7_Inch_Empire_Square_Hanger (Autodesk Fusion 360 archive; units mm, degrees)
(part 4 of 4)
sketch "Front_Common_Rafter_Text" plane through (0, 0, 0) normal (0, 1, 0) x axis (1, 0, 0)
  line L1 (177.8, 1.5875) -> (0, 1.5875)
  line L2 (0, 1.5875) -> (0, -176.2125)
  line L3 (0, -176.2125) -> (177.8, 1.5875)
  line L4 (176.2125, 0) -> (0, 0)
  line L5 (131.4823, -11.5032) -> (124.2435, -10.8699)
  line L6 (122.4881, -20.4975) -> (116.3338, -19.4676)
  line L7 (114.45, -28.5356) -> (108.6995, -27.1018)
  line L8 (107.1378, -35.8478) -> (101.7547, -34.0466)
  line L9 (101.1061, -41.8795) -> (96.0261, -39.7753)
  line L10 (95.4139, -47.5716) -> (90.6199, -45.1814)
  line L11 (90.3153, -52.6703) -> (85.2289, -49.704)
  line L12 (85.7136, -57.272) -> (81.407, -54.3944)
  line L13 (81.5404, -61.4451) -> (77.4435, -58.3579)
  line L14 (78.062, -64.9235) -> (74.1399, -61.6615)
  line L15 (74.6142, -68.3713) -> (70.3971, -64.5071)
  line L16 (71.4928, -71.4928) -> (67.4517, -67.4517)
  line L17 (68.6213, -74.3642) -> (65.1735, -70.6278)
  line L18 (65.9917, -76.9938) -> (62.2628, -72.6432)
  line L19 (63.5999, -79.3857) -> (60.4044, -75.397)
  line L20 (61.3178, -81.6677) -> (58.237, -77.5644)
  line L21 (59.1438, -83.8417) -> (56.1722, -79.6292)
  line L22 (57.2071, -85.7784) -> (53.9805, -80.9403)
  line L23 (55.3812, -87.6044) -> (52.5986, -83.2028)
  line L24 (53.6676, -89.3179) -> (50.9711, -84.8302)
  line L25 (51.9346, -91.051) -> (49.3252, -86.4762)
  line L26 (50.4513, -92.5342) -> (47.9164, -87.8849)
  line L27 (49.0883, -93.8973) -> (46.3277, -88.6167)
  line L28 (47.7103, -95.2753) -> (45.3132, -90.4883)
  line L29 (134.6309, -8.3546) -> (41.6921, -101.2934)
  line L30 (131.0388, -4.7625) -> (38.1, -97.7013)
  line L31 (133.7069, -12.8708) -> (135.864, -10.7136)
  line L32 (134.7855, -11.7922) -> (131.4823, -11.5032)
  line L33 (131.4823, -11.5032) -> (124.8761, -10.9252)
  line L34 (125.5652, -21.0124) -> (122.4881, -20.4975)
  line L35 (124.4929, -22.0847) -> (126.6376, -19.9401)
  line L36 (117.3252, -29.2525) -> (114.45, -28.5356)
  line L37 (119.0808, -27.4969) -> (115.5696, -31.0081)
  line L38 (109.8293, -36.7484) -> (107.1378, -35.8478)
  line L39 (103.6461, -42.9316) -> (101.1061, -41.8795)
  line L40 (97.8109, -48.7667) -> (95.4139, -47.5716)
  line L41 (92.5842, -53.9935) -> (90.3153, -52.6703)
  line L42 (87.8669, -58.7108) -> (85.7136, -57.272)
  line L43 (104.7965, -41.7812) -> (102.4956, -44.0821)
  line L44 (98.9884, -47.5892) -> (96.6334, -49.9442)
  line L45 (93.6043, -52.9734) -> (91.5641, -55.0136)
  line L46 (89.01, -57.5676) -> (86.7237, -59.8539)
  line L47 (83.5889, -62.9888) -> (81.5404, -61.4451)
  line L48 (48.9089, -97.6688) -> (47.7103, -95.2753)
  line L49 (50.3215, -96.2562) -> (49.0883, -93.8973)
  line L50 (51.7188, -94.8589) -> (50.4513, -92.5342)
  line L51 (53.2393, -93.3384) -> (51.9346, -91.051)
  line L52 (55.0159, -91.5618) -> (53.6676, -89.3179)
  line L53 (56.7725, -89.8052) -> (55.3812, -87.6044)
  line L54 (58.6443, -87.9334) -> (57.2071, -85.7784)
  line L55 (60.6296, -85.948) -> (59.1438, -83.8417)
  line L56 (62.8583, -83.7194) -> (61.3178, -81.6677)
  line L57 (65.1977, -81.38) -> (63.5999, -79.3857)
  line L58 (67.6496, -78.9281) -> (65.9917, -76.9938)
  line L59 (70.3452, -76.2324) -> (68.6213, -74.3642)
  line L60 (73.2888, -73.2888) -> (71.4928, -71.4928)
  line L61 (76.4887, -70.089) -> (74.6142, -68.3713)
  line L62 (80.0231, -66.5545) -> (78.062, -64.9235)
  line L63 (84.8131, -61.7645) -> (82.3647, -64.213)
  line L64 (81.1425, -65.4352) -> (78.9038, -67.6739)
  line L65 (77.5939, -68.9838) -> (75.3835, -71.1941)
  line L66 (74.3554, -72.2223) -> (72.2223, -74.3554)
  line L67 (71.4477, -75.13) -> (69.2428, -77.3349)
  line L68 (68.6194, -77.9583) -> (66.6798, -79.8979)
  line L69 (65.9607, -80.6169) -> (64.4346, -82.143)
  line L70 (63.6278, -82.9499) -> (62.0888, -84.4888)
  line L71 (61.3516, -85.2261) -> (59.9077, -86.67)
  line L72 (59.0519, -87.5258) -> (58.2367, -88.341)
  line L73 (57.1706, -89.407) -> (56.3743, -90.2033)
  line L74 (55.3816, -91.1961) -> (54.6502, -91.9275)
  line L75 (53.6549, -92.9227) -> (52.8236, -93.754)
  line L76 (52.0292, -94.5485) -> (51.4083, -95.1693)
  line L77 (50.7174, -95.8602) -> (49.9256, -96.6521)
  line L78 (49.3359, -97.2417) -> (48.4818, -98.0958)
  line L79 (110.6422, -35.9355) -> (109.0164, -37.5613)
  line L80 (30.6283, -115.9494) -> (40.2487, -106.329)
  point P11 (131.4823, -11.5032)
  point P64 (131.4823, -11.5032)
  point P65 (134.7855, -11.7922)
  point P68 (125.5652, -21.0124)
  point P13 (122.4881, -20.4975)
  point P71 (122.4881, -20.4975)
  point P15 (114.45, -28.5356)
  point P72 (114.45, -28.5356)
  point P73 (117.3252, -29.2525)
  point P17 (107.1378, -35.8478)
  point P76 (107.1378, -35.8478)
  point P19 (101.1061, -41.8795)
  point P78 (101.1061, -41.8795)
  point P21 (95.4139, -47.5716)
  point P80 (95.4139, -47.5716)
  point P23 (90.3153, -52.6703)
  point P82 (90.3153, -52.6703)
  point P25 (85.7136, -57.272)
  point P84 (85.7136, -57.272)
  point P27 (81.5404, -61.4451)
  point P94 (81.5404, -61.4451)
  point P57 (47.7103, -95.2753)
  point P96 (47.7103, -95.2753)
  point P55 (49.0883, -93.8973)
  point P98 (49.0883, -93.8973)
  point P53 (50.4513, -92.5342)
  point P100 (50.4513, -92.5342)
  point P51 (51.9346, -91.051)
  point P102 (51.9346, -91.051)
  point P49 (53.6676, -89.3179)
  point P104 (53.6676, -89.3179)
  point P47 (55.3812, -87.6044)
  point P106 (55.3812, -87.6044)
  point P45 (57.2071, -85.7784)
  point P108 (57.2071, -85.7784)
  point P43 (59.1438, -83.8417)
  point P110 (59.1438, -83.8417)
  point P41 (61.3178, -81.6677)
  point P112 (61.3178, -81.6677)
  point P39 (63.5999, -79.3857)
  point P114 (63.5999, -79.3857)
  point P37 (65.9917, -76.9938)
  point P116 (65.9917, -76.9938)
  point P35 (68.6213, -74.3642)
  point P118 (68.6213, -74.3642)
  point P33 (71.4928, -71.4928)
  point P120 (71.4928, -71.4928)
  point P31 (74.6142, -68.3713)
  point P122 (74.6142, -68.3713)
  point P29 (78.062, -64.9235)
  point P124 (78.062, -64.9235)
  point P97 (48.9089, -97.6688)
  point P99 (50.3215, -96.2562)
  point P101 (51.7188, -94.8589)
  point P103 (53.2393, -93.3384)
  point P105 (55.0159, -91.5618)
  point P107 (56.7725, -89.8052)
  point P109 (58.6443, -87.9334)
  point P111 (60.6296, -85.948)
  point P113 (62.8583, -83.7194)
  point P115 (65.1977, -81.38)
  point P117 (67.6496, -78.9281)
  point P119 (70.3452, -76.2324)
  point P121 (73.2888, -73.2888)
  point P123 (76.4887, -70.089)
  point P125 (80.0231, -66.5545)
  point P95 (83.5889, -62.9888)
  point P85 (87.8669, -58.7108)
  point P83 (92.5842, -53.9935)
  point P81 (97.8109, -48.7667)
  point P79 (103.6461, -42.9316)
  point P77 (109.8293, -36.7484)
  point P162 (35.4385, -111.1392)
  point P62 (135.864, -10.7136)
  coincident P11 P64
  midpoint L31 P65
  parallel L32 L33
  parallel L29 L31
  midpoint P68 L35
  coincident P13 P71
  parallel L6 L34
  collinear L31 L35
  coincident P15 P72
  parallel L7 L36
  midpoint P73 L37
  collinear L35 L37
  coincident P17 P76
  parallel L8 L38
  coincident P19 P78
  parallel L9 L39
  coincident P21 P80
  parallel L10 L40
  coincident P23 P82
  parallel L11 L41
  coincident P25 P84
  parallel L12 L42
  coincident P27 P94
  parallel L13 L47
  coincident P57 P96
  parallel L28 L48
  coincident P55 P98
  parallel L27 L49
  coincident P53 P100
  parallel L26 L50
  coincident P51 P102
  parallel L25 L51
  coincident P49 P104
  parallel L24 L52
  coincident P47 P106
  parallel L23 L53
  coincident P45 P108
  parallel L22 L54
  coincident P43 P110
  parallel L21 L55
  coincident P41 P112
  parallel L20 L56
  coincident P39 P114
  parallel L19 L57
  coincident P37 P116
  parallel L18 L58
  coincident P35 P118
  coincident P33 P120
  parallel L17 L59
  parallel L16 L60
  coincident P31 P122
  parallel L15 L61
  coincident P29 P124
  parallel L14 L62
  midpoint P97 L78
  midpoint P99 L77
  midpoint P101 L76
  midpoint P103 L75
  midpoint P105 L74
  midpoint P107 L73
  midpoint P109 L72
  midpoint P111 L71
  midpoint P113 L70
  midpoint P115 L69
  midpoint P117 L68
  midpoint P119 L67
  midpoint P121 L66
  midpoint P123 L65
  midpoint P125 L64
  midpoint P95 L63
  midpoint P85 L46
  midpoint P83 L45
  midpoint P81 L44
  midpoint P79 L43
  midpoint P77 L79
  collinear L37 L79
  collinear L43 L79
  collinear L43 L44
  collinear L44 L45
  collinear L45 L46
  collinear L46 L63
  collinear L63 L64
  collinear L64 L65
  collinear L65 L66
  collinear L66 L67
  collinear L67 L68
  collinear L68 L69
  collinear L69 L70
  collinear L70 L71
  collinear L71 L72
  collinear L72 L73
  collinear L73 L74
  collinear L74 L75
  collinear L75 L76
  collinear L76 L77
  collinear L77 L78
  collinear L78 L80
  midpoint L80 P162
  dimension "d956" distance L29 P62 = 2.54
  dimension "d1030" distance P97 P162 = 19.05
  dimension "d957" Text1-Height = 3.175
  dimension "d958" Text2-Height = 3.175
  dimension "d959" Text3-Height = 3.175
  dimension "d960" Text4-Height = 3.175
  dimension "d961" Text5-Height = 3.175
  dimension "d962" Text6-Height = 3.175
  dimension "d963" Text7-Height = 3.175
  dimension "d964" Text8-Height = 3.175
  dimension "d965" Text9-Height = 3.175
  dimension "d966" Text10-Height = 3.175
  dimension "d968" Text11-Height = 3.175
  dimension "d969" Text12-Height = 3.175
  dimension "d970" Text13-Height = 3.175
  dimension "d971" Text14-Height = 3.175
  dimension "d1029" Text15-Height = 3.175
sketch "Back_Common_Rafter_Text" plane through (0, 0, 0) normal (0, 1, 0) x axis (1, 0, 0)
  line L1 (71.4477, -75.13) -> (69.2428, -77.3349)
  line L2 (70.3452, -76.2324) -> (68.6212, -74.3641)
  line L3 (63.6278, -82.9499) -> (62.0888, -84.4888)
  line L4 (65.1977, -81.38) -> (63.5997, -79.3854)
  line L5 (89.01, -57.5676) -> (86.7237, -59.8539)
  line L6 (73.2888, -73.2888) -> (71.4922, -71.4922)
  line L7 (65.9915, -76.9936) -> (62.2628, -72.6432)
  line L8 (68.6194, -77.9583) -> (66.6798, -79.8979)
  line L9 (67.6496, -78.9281) -> (65.9915, -76.9936)
  line L10 (76.4887, -70.089) -> (74.6141, -68.3712)
  line L11 (62.8583, -83.7194) -> (61.3178, -81.6677)
  line L12 (77.5939, -68.9838) -> (75.3835, -71.1941)
  line L13 (110.6422, -35.9355) -> (109.0164, -37.5612)
  line L14 (68.6212, -74.3641) -> (65.1735, -70.6278)
  line L15 (84.8131, -61.7645) -> (82.3647, -64.213)
  line L16 (98.9884, -47.5892) -> (96.6334, -49.9442)
  line L17 (124.4929, -22.0847) -> (126.6376, -19.9401)
  line L18 (104.7965, -41.7811) -> (102.4956, -44.0821)
  line L19 (65.9607, -80.6169) -> (64.4346, -82.143)
  line L20 (59.0519, -87.5258) -> (58.2367, -88.341)
  line L21 (133.7069, -12.8708) -> (135.864, -10.7136)
  line L22 (119.0811, -27.4965) -> (115.5693, -31.0084)
  line L23 (74.3554, -72.2223) -> (72.2223, -74.3554)
  line L24 (81.1425, -65.4352) -> (78.9038, -67.6739)
  line L25 (93.6053, -52.9723) -> (91.5651, -55.0125)
  line L26 (49.3359, -97.2418) -> (48.4819, -98.0958)
  line L27 (53.6549, -92.9227) -> (52.8236, -93.7541)
  line L28 (61.3516, -85.2261) -> (59.9077, -86.67)
  line L29 (48.9089, -97.6688) -> (47.7103, -95.2753)
  line L30 (61.3178, -81.6677) -> (58.237, -77.5644)
  line L31 (63.5997, -79.3854) -> (60.4044, -75.397)
  line L32 (71.4922, -71.4922) -> (67.4517, -67.4517)
  line L33 (74.6141, -68.3712) -> (70.3971, -64.5071)
  line L34 (90.3157, -52.6694) -> (85.2289, -49.704)
  line L35 (134.7855, -11.7922) -> (131.4328, -11.4989)
  line L36 (103.6461, -42.9316) -> (101.1059, -41.8794)
  line L37 (114.45, -28.5356) -> (108.6995, -27.1018)
  line L38 (87.8669, -58.7108) -> (85.7135, -57.2719)
  line L39 (107.1376, -35.8477) -> (101.7547, -34.0466)
  line L40 (125.5652, -21.0124) -> (122.4881, -20.4975)
  line L41 (55.3808, -87.6038) -> (52.5986, -83.2028)
  line L42 (57.1706, -89.407) -> (56.3743, -90.2033)
  line L43 (101.1059, -41.8794) -> (96.0261, -39.7753)
  line L44 (97.8109, -48.7667) -> (95.4136, -47.5715)
  line L45 (122.4881, -20.4975) -> (116.3338, -19.4676)
  line L46 (53.2393, -93.3384) -> (51.9336, -91.0493)
  line L47 (55.0159, -91.5618) -> (53.6671, -89.317)
  line L48 (81.5404, -61.4451) -> (77.4435, -58.3579)
  line L49 (83.5889, -62.9888) -> (81.5404, -61.4451)
  line L50 (78.0619, -64.9234) -> (74.1399, -61.6615)
  line L51 (117.3252, -29.2525) -> (114.45, -28.5356)
  line L52 (57.2071, -85.7784) -> (53.9805, -80.9403)
  line L53 (80.0231, -66.5545) -> (78.0619, -64.9234)
  line L54 (47.7103, -95.2753) -> (45.3132, -90.4883)
  line L55 (85.7135, -57.2719) -> (81.407, -54.3944)
  line L56 (92.5852, -53.9924) -> (90.3157, -52.6694)
  line L57 (51.9336, -91.0493) -> (49.3252, -86.4762)
  line L58 (51.7188, -94.8589) -> (50.4504, -92.5326)
  line L59 (50.7174, -95.8602) -> (49.9256, -96.6521)
  line L60 (131.4328, -11.4989) -> (124.2435, -10.8699)
  line L61 (109.8293, -36.7484) -> (107.1376, -35.8477)
  line L62 (50.3215, -96.2562) -> (49.0879, -93.8964)
  line L63 (56.7725, -89.8052) -> (55.3808, -87.6038)
  line L64 (52.0292, -94.5485) -> (51.4083, -95.1693)
  line L65 (59.1427, -83.8401) -> (56.1722, -79.6292)
  line L66 (131.4823, -11.5032) -> (124.8761, -10.9252)
  line L67 (58.6443, -87.9334) -> (57.2071, -85.7784)
  line L68 (50.4504, -92.5326) -> (47.9164, -87.8849)
  line L69 (53.6671, -89.317) -> (50.9711, -84.8302)
  line L70 (60.6296, -85.948) -> (59.1427, -83.8401)
  line L71 (95.4136, -47.5715) -> (90.6199, -45.1814)
  line L72 (49.0879, -93.8964) -> (46.3277, -88.6167)
  line L73 (55.3816, -91.1961) -> (54.6502, -91.9275)
  line L74 (176.2125, 0) -> (0, 0)
  line L75 (177.8, 1.5875) -> (0, 1.5875)
  line L76 (0, 1.5875) -> (0, -176.2125)
  line L77 (0, -176.2125) -> (177.8, 1.5875)
  line L78 (49.0883, -93.8973) -> (46.3277, -88.6167)
  line L79 (50.4513, -92.5342) -> (47.9164, -87.8849)
  line L80 (51.9346, -91.051) -> (49.3252, -86.4762)
  line L81 (53.6676, -89.3179) -> (50.9711, -84.8302)
  line L82 (48.9089, -97.6688) -> (47.7103, -95.2753)
  line L83 (55.3812, -87.6044) -> (52.5986, -83.2028)
  line L84 (59.1438, -83.8417) -> (56.1722, -79.6292)
  line L85 (63.5999, -79.3857) -> (60.4044, -75.397)
  line L86 (65.9917, -76.9938) -> (62.2628, -72.6432)
  line L87 (68.6213, -74.3642) -> (65.1735, -70.6278)
  line L88 (71.4928, -71.4928) -> (67.4517, -67.4517)
  line L89 (74.6142, -68.3713) -> (70.3971, -64.5071)
  line L90 (78.062, -64.9235) -> (74.1399, -61.6615)
  line L91 (81.5404, -61.4451) -> (77.4435, -58.3579)
  line L92 (85.7136, -57.272) -> (81.407, -54.3944)
  line L93 (95.4139, -47.5716) -> (90.6199, -45.1814)
  line L94 (101.1061, -41.8795) -> (96.0261, -39.7753)
  line L95 (107.1378, -35.8478) -> (101.7547, -34.0466)
  line L96 (114.45, -28.5356) -> (108.6995, -27.1018)
  line L97 (131.4823, -11.5032) -> (124.8761, -10.9252)
  line L98 (131.4823, -11.5032) -> (124.2435, -10.8699)
  line L99 (131.0388, -4.7625) -> (38.1, -97.7013)
  line L100 (134.6309, -8.3546) -> (41.6921, -101.2934)
  line L101 (125.5652, -21.0124) -> (122.4881, -20.4975)
  line L102 (62.8583, -83.7194) -> (61.3178, -81.6677)
  line L103 (30.6283, -115.9494) -> (40.2487, -106.329)
  point P16 (131.4328, -11.4989)
  point P79 (131.4328, -11.4989)
  point P82 (134.7855, -11.7922)
  point P8 (125.5652, -21.0124)
  point P11 (122.4881, -20.4975)
  point P23 (122.4881, -20.4975)
  point P4 (114.45, -28.5356)
  point P26 (114.45, -28.5356)
  point P5 (117.3252, -29.2525)
  point P24 (107.1376, -35.8477)
  point P51 (107.1376, -35.8477)
  point P27 (101.1059, -41.8794)
  point P52 (101.1059, -41.8794)
  point P18 (95.4136, -47.5715)
  point P116 (95.4136, -47.5715)
  point P31 (90.3157, -52.6694)
  point P67 (90.3157, -52.6694)
  point P35 (85.7135, -57.2719)
  point P114 (85.7135, -57.2719)
  point P68 (81.5404, -61.4451)
  point P130 (81.5404, -61.4451)
  point P85 (47.7103, -95.2753)
  point P136 (47.7103, -95.2753)
  point P69 (49.0879, -93.8964)
  point P88 (49.0879, -93.8964)
  point P89 (50.4504, -92.5326)
  point P138 (50.4504, -92.5326)
  point P38 (51.9336, -91.0493)
  point P84 (51.9336, -91.0493)
  point P58 (53.6671, -89.317)
  point P77 (53.6671, -89.317)
  point P76 (55.3808, -87.6038)
  point P128 (55.3808, -87.6038)
  point P34 (59.1427, -83.8401)
  point P107 (59.1427, -83.8401)
  point P105 (61.3178, -81.6677)
  point P142 (61.3178, -81.6677)
  point P103 (63.5997, -79.3854)
  point P110 (63.5997, -79.3854)
  point P101 (65.9915, -76.9936)
  point P115 (65.9915, -76.9936)
  point P50 (68.6212, -74.3641)
  point P60 (68.6212, -74.3641)
  point P2 (71.4922, -71.4922)
  point P48 (71.4922, -71.4922)
  point P29 (74.6141, -68.3712)
  point P65 (74.6141, -68.3712)
  point P113 (78.0619, -64.9234)
  point P123 (78.0619, -64.9234)
  point P137 (48.9089, -97.6688)
  point P70 (50.3215, -96.2562)
  point P140 (51.7188, -94.8589)
  point P44 (53.2393, -93.3384)
  point P54 (55.0159, -91.5618)
  point P124 (56.7725, -89.8052)
  point P41 (58.6443, -87.9334)
  point P108 (60.6296, -85.948)
  point P133 (62.8583, -83.7194)
  point P147 (65.1977, -81.38)
  point P62 (67.6496, -78.9281)
  point P64 (70.3452, -76.2324)
  point P3 (73.2888, -73.2888)
  point P63 (76.4887, -70.089)
  point P126 (80.0231, -66.5545)
  point P139 (83.5889, -62.9888)
  point P33 (87.8669, -58.7108)
  point P32 (92.5852, -53.9924)
  point P117 (97.8109, -48.7667)
  point P118 (103.6461, -42.9316)
  point P53 (109.8293, -36.7484)
  point P90 (45.3132, -90.4883)
  point P156 (45.3132, -90.4883)
  point P86 (46.3277, -88.6167)
  point P157 (46.3277, -88.6167)
  point P80 (47.9164, -87.8849)
  point P160 (47.9164, -87.8849)
  point P78 (49.3252, -86.4762)
  point P163 (49.3252, -86.4762)
  point P75 (50.9711, -84.8302)
  point P166 (50.9711, -84.8302)
  point P169 (47.7103, -95.2753)
  point P74 (52.5986, -83.2028)
  point P172 (52.5986, -83.2028)
  point P73 (53.9805, -80.9403)
  point P175 (53.9805, -80.9403)
  point P30 (56.1722, -79.6292)
  point P176 (56.1722, -79.6292)
  point P104 (58.237, -77.5644)
  point P179 (58.237, -77.5644)
  point P102 (60.4044, -75.397)
  point P180 (60.4044, -75.397)
  point P49 (62.2628, -72.6432)
  point P183 (62.2628, -72.6432)
  point P47 (65.1735, -70.6278)
  point P186 (65.1735, -70.6278)
  point P46 (67.4517, -67.4517)
  point P189 (67.4517, -67.4517)
  point P28 (70.3971, -64.5071)
  point P192 (70.3971, -64.5071)
  point P111 (74.1399, -61.6615)
  point P195 (74.1399, -61.6615)
  point P20 (77.4435, -58.3579)
  point P198 (77.4435, -58.3579)
  point P112 (81.407, -54.3944)
  point P201 (81.407, -54.3944)
  point P17 (85.2289, -49.704)
  point P204 (85.2289, -49.704)
  point P15 (90.6199, -45.1814)
  point P205 (90.6199, -45.1814)
  point P21 (96.0261, -39.7753)
  point P208 (96.0261, -39.7753)
  point P25 (101.7547, -34.0466)
  point P211 (101.7547, -34.0466)
  point P14 (108.6995, -27.1018)
  point P214 (108.6995, -27.1018)
  point P22 (116.3338, -19.4676)
  point P217 (116.3338, -19.4676)
  point P81 (124.8761, -10.9252)
  point P218 (124.8761, -10.9252)
  point P19 (124.2435, -10.8699)
  point P221 (124.2435, -10.8699)
  point P228 (122.4881, -20.4975)
  point P231 (61.3178, -81.6677)
  point P43 (57.2071, -85.7784)
  point P234 (57.2071, -85.7784)
  coincident P16 P79
  midpoint P82 L21
  parallel L35 L66
  midpoint P8 L17
  coincident P11 P23
  parallel L40 L45
  collinear L17 L21
  coincident P4 P26
  parallel L37 L51
  midpoint P5 L22
  collinear L17 L22
  coincident P24 P51
  parallel L39 L61
  coincident P27 P52
  parallel L36 L43
  coincident P18 P116
  parallel L44 L71
  coincident P31 P67
  parallel L34 L56
  coincident P35 P114
  parallel L38 L55
  coincident P68 P130
  parallel L48 L49
  coincident P85 P136
  parallel L29 L54
  coincident P69 P88
  parallel L62 L72
  coincident P89 P138
  parallel L58 L68
  coincident P38 P84
  parallel L46 L57
  coincident P58 P77
  parallel L47 L69
  coincident P76 P128
  parallel L41 L63
  parallel L52 L67
  coincident P34 P107
  parallel L65 L70
  coincident P105 P142
  parallel L11 L30
  coincident P103 P110
  parallel L4 L31
  coincident P101 P115
  parallel L7 L9
  coincident P50 P60
  coincident P2 P48
  parallel L2 L14
  parallel L6 L32
  coincident P29 P65
  parallel L10 L33
  coincident P113 P123
  parallel L50 L53
  midpoint P137 L26
  midpoint P70 L59
  midpoint P140 L64
  midpoint P44 L27
  midpoint P54 L73
  midpoint P124 L42
  midpoint P41 L20
  midpoint P108 L28
  midpoint P133 L3
  midpoint P147 L19
  midpoint P62 L8
  midpoint P64 L1
  midpoint P3 L23
  midpoint P63 L12
  midpoint P126 L24
  midpoint P139 L15
  midpoint P33 L5
  midpoint P32 L25
  midpoint P117 L16
  midpoint P118 L18
  midpoint P53 L13
  collinear L13 L22
  collinear L13 L18
  collinear L16 L18
  collinear L16 L25
  collinear L5 L25
  collinear L5 L15
  collinear L15 L24
  collinear L12 L24
  collinear L12 L23
  collinear L1 L23
  collinear L1 L8
  collinear L8 L19
  collinear L3 L19
  collinear L3 L28
  collinear L20 L28
  collinear L20 L42
  collinear L42 L73
  collinear L27 L73
  collinear L27 L64
  collinear L59 L64
  collinear L26 L59
  coincident P90 P156
  coincident P86 P157
  parallel L72 L78
  coincident P80 P160
  parallel L68 L79
  coincident P78 P163
  parallel L57 L80
  coincident P75 P166
  parallel L69 L81
  coincident P136 P169
  coincident P74 P172
  parallel L41 L83
  coincident P73 P175
  coincident P30 P176
  parallel L65 L84
  coincident P104 P179
  coincident P102 P180
  parallel L31 L85
  coincident P49 P183
  parallel L7 L86
  coincident P47 P186
  parallel L14 L87
  coincident P46 P189
  parallel L32 L88
  coincident P28 P192
  parallel L33 L89
  coincident P111 P195
  parallel L50 L90
  coincident P20 P198
  parallel L48 L91
  coincident P112 P201
  parallel L55 L92
  coincident P17 P204
  coincident P15 P205
  parallel L71 L93
  coincident P21 P208
  parallel L43 L94
  coincident P25 P211
  parallel L39 L95
  coincident P14 P214
  parallel L37 L96
  coincident P22 P217
  coincident P81 P218
  parallel L66 L97
  coincident P19 P221
  parallel L60 L98
  coincident P11 P228
  parallel L21 L100
  coincident P142 L100
  coincident P142 P231
  coincident P43 P234
  dimension "d988" distance L21 L100 = 2.54
  dimension "d972" Text1-Height = 3.175
  dimension "d973" Text2-Height = 3.175
  dimension "d974" Text3-Height = 3.175
  dimension "d975" Text4-Height = 3.175
  dimension "d976" Text5-Height = 3.175
  dimension "d977" Text6-Height = 3.175
  dimension "d978" Text7-Height = 3.175
  dimension "d979" Text8-Height = 3.175
  dimension "d980" Text9-Height = 3.175
  dimension "d981" Text10-Height = 3.175
  dimension "d982" Text11-Height = 3.175
  dimension "d983" Text12-Height = 3.175
  dimension "d984" Text13-Height = 3.175
  dimension "d985" Text14-Height = 3.175
  dimension "d1031" Text15-Height = 3.175
sketch "Front_Hip-Valley_Text" plane through (0, 0, 0) normal (0, 1, 0) x axis (1, 0, 0)
  line L1 (0, 1.5875) -> (0, -176.2125)
  line L2 (177.8, 1.5875) -> (0, 1.5875)
  line L3 (0, -176.2125) -> (177.8, 1.5875)
  line L4 (34.5079, -85.129) -> (118.4665, -1.1704)
  line L5 (38.1, -88.7211) -> (122.0586, -4.7625)
  line L6 (52.8926, -74.8136) -> (49.5505, -70.0864)
  line L7 (54.2202, -73.4888) -> (50.7931, -68.8438)
  line L8 (55.6191, -72.0926) -> (52.1025, -67.5344)
  line L9 (57.0778, -70.6363) -> (53.4679, -66.169)
  line L10 (58.6192, -69.0969) -> (54.911, -64.7259)
  line L11 (60.255, -67.4627) -> (56.4427, -63.1942)
  line L12 (61.9752, -65.7435) -> (58.0535, -61.5834)
  line L13 (63.8038, -63.9153) -> (59.7662, -59.8706)
  line L14 (65.7435, -61.9752) -> (61.5834, -58.0535)
  line L15 (67.798, -59.9194) -> (63.5085, -56.1284)
  line L16 (69.9838, -57.7312) -> (65.5572, -54.0797)
  line L17 (72.3191, -55.3922) -> (67.7468, -51.8901)
  line L18 (74.8021, -52.9041) -> (70.0756, -49.5613)
  line L19 (77.4796, -50.2198) -> (72.5878, -47.0491)
  line L20 (80.3449, -47.3457) -> (75.2774, -44.3595)
  line L21 (83.4307, -44.2489) -> (78.1753, -41.4616)
  line L22 (86.7641, -40.9021) -> (81.3072, -38.3296)
  line L23 (90.3668, -37.2834) -> (84.694, -34.9429)
  line L24 (94.2953, -33.3362) -> (88.3888, -31.2481)
  line L25 (98.5635, -29.0462) -> (92.4054, -27.2315)
  line L26 (103.2529, -24.3319) -> (96.8208, -22.8161)
  line L27 (108.3869, -19.1701) -> (101.6571, -17.9798)
  line L28 (114.0839, -13.4422) -> (107.0263, -12.6106)
  line L29 (117.1566, -10.3529) -> (109.9232, -9.7137)
  line L30 (106.6227, -9.422) -> (109.9232, -9.7137)
  line L31 (103.8128, -12.2319) -> (107.0263, -12.6106)
  line L32 (98.6048, -17.4399) -> (101.6571, -17.9798)
  line L33 (93.9137, -22.131) -> (96.8208, -22.8161)
  line L34 (89.631, -26.4138) -> (92.4054, -27.2315)
  line L35 (85.735, -30.3098) -> (88.3888, -31.2481)
  line L36 (82.151, -33.8938) -> (84.694, -34.9429)
  line L37 (78.866, -37.1788) -> (81.3072, -38.3296)
  line L38 (75.8281, -40.2167) -> (78.1753, -41.4616)
  line L39 (73.0172, -43.0276) -> (75.2774, -44.3595)
  line L40 (70.4084, -45.6364) -> (72.5878, -47.0491)
  line L41 (67.9716, -48.0732) -> (70.0756, -49.5613)
  line L42 (65.7127, -50.3321) -> (67.7468, -51.8901)
  line L43 (63.5889, -52.4559) -> (65.5572, -54.0797)
  line L44 (61.6017, -54.4431) -> (63.5085, -56.1284)
  line L45 (59.7343, -56.3105) -> (61.5834, -58.0535)
  line L46 (57.9718, -58.073) -> (59.7662, -59.8706)
  line L47 (56.3105, -59.7343) -> (58.0535, -61.5834)
  line L48 (54.748, -61.2968) -> (56.4427, -63.1942)
  line L49 (53.2623, -62.7825) -> (54.911, -64.7259)
  line L50 (51.8626, -64.1822) -> (53.4679, -66.169)
  line L51 (50.5381, -65.5067) -> (52.1025, -67.5344)
  line L52 (49.268, -66.7767) -> (50.7931, -68.8438)
  line L53 (48.0627, -67.982) -> (49.5505, -70.0864)
  line L54 (103.1183, -12.9265) -> (104.5074, -11.5374)
  line L55 (97.292, -18.7528) -> (99.9177, -16.1271)
  line L56 (92.1996, -23.8452) -> (95.6279, -20.4169)
  line L57 (88.2354, -27.8094) -> (91.0265, -25.0183)
  line L58 (84.4206, -31.6242) -> (87.0493, -28.9955)
  line L59 (80.7488, -35.2959) -> (83.5532, -32.4916)
  line L60 (77.7876, -38.2571) -> (79.9443, -36.1004)
  line L61 (74.8024, -41.2424) -> (76.8537, -39.191)
  line L62 (72.0594, -43.9854) -> (73.975, -42.0698)
  line L63 (69.9763, -46.0685) -> (70.8404, -45.2044)
  line L64 (67.268, -48.7767) -> (68.6752, -47.3696)
  line L65 (65.1884, -50.8563) -> (66.237, -49.8078)
  line L66 (63.0246, -53.0202) -> (64.1532, -51.8916)
  line L67 (60.777, -55.2677) -> (62.4263, -53.6185)
  line L68 (59.2472, -56.7975) -> (60.2214, -55.8234)
  line L69 (57.3665, -58.6783) -> (58.577, -57.4678)
  line L70 (55.8285, -60.2162) -> (56.7924, -59.2524)
  line L71 (54.2489, -61.7959) -> (55.247, -60.7977)
  line L72 (52.7738, -63.271) -> (53.7508, -62.294)
  line L73 (51.3925, -64.6523) -> (52.3326, -63.7121)
  line L74 (50.1827, -65.8621) -> (50.8935, -65.1513)
  line L75 (48.9243, -67.1205) -> (49.6118, -66.433)
  line L76 (47.7139, -68.3308) -> (48.4116, -67.6332)
  line L77 (105.3862, -10.6586) -> (107.8593, -8.1855)
  line L78 (28.4126, -87.6321) -> (40.7721, -75.2727)
  point P58 (109.9232, -9.7137)
  point P60 (109.9232, -9.7137)
  point P61 (106.6227, -9.422)
  point P62 (103.8128, -12.2319)
  point P54 (101.6571, -17.9798)
  point P63 (101.6571, -17.9798)
  point P64 (98.6048, -17.4399)
  point P52 (96.8208, -22.8161)
  point P65 (96.8208, -22.8161)
  point P66 (93.9137, -22.131)
  point P50 (92.4054, -27.2315)
  point P67 (92.4054, -27.2315)
  point P68 (89.631, -26.4138)
  point P48 (88.3888, -31.2481)
  point P69 (88.3888, -31.2481)
  point P70 (85.735, -30.3098)
  point P46 (84.694, -34.9429)
  point P71 (84.694, -34.9429)
  point P72 (82.151, -33.8938)
  point P44 (81.3072, -38.3296)
  point P73 (81.3072, -38.3296)
  point P74 (78.866, -37.1788)
  point P42 (78.1753, -41.4616)
  point P75 (78.1753, -41.4616)
  point P76 (75.8281, -40.2167)
  point P40 (75.2774, -44.3595)
  point P77 (75.2774, -44.3595)
  point P78 (73.0172, -43.0276)
  point P79 (70.4084, -45.6364)
  point P36 (70.0756, -49.5613)
  point P80 (70.0756, -49.5613)
  point P81 (67.9716, -48.0732)
  point P38 (72.5878, -47.0491)
  point P82 (72.5878, -47.0491)
  point P56 (107.0263, -12.6106)
  point P83 (107.0263, -12.6106)
  point P34 (67.7468, -51.8901)
  point P84 (67.7468, -51.8901)
  point P85 (65.7127, -50.3321)
  point P32 (65.5572, -54.0797)
  point P86 (65.5572, -54.0797)
  point P87 (63.5889, -52.4559)
  point P30 (63.5085, -56.1284)
  point P88 (63.5085, -56.1284)
  point P89 (61.6017, -54.4431)
  point P28 (61.5834, -58.0535)
  point P90 (61.5834, -58.0535)
  point P91 (59.7343, -56.3105)
  point P26 (59.7662, -59.8706)
  point P92 (59.7662, -59.8706)
  point P93 (57.9718, -58.073)
  point P24 (58.0535, -61.5834)
  point P94 (58.0535, -61.5834)
  point P95 (56.3105, -59.7343)
  point P22 (56.4427, -63.1942)
  point P96 (56.4427, -63.1942)
  point P97 (54.748, -61.2968)
  point P20 (54.911, -64.7259)
  point P98 (54.911, -64.7259)
  point P99 (53.2623, -62.7825)
  point P18 (53.4679, -66.169)
  point P100 (53.4679, -66.169)
  point P101 (51.8626, -64.1822)
  point P16 (52.1025, -67.5344)
  point P102 (52.1025, -67.5344)
  point P103 (50.5381, -65.5067)
  point P104 (49.268, -66.7767)
  point P12 (49.5505, -70.0864)
  point P105 (49.5505, -70.0864)
  point P106 (48.0627, -67.982)
  point P14 (50.7931, -68.8438)
  point P107 (50.7931, -68.8438)
  point P158 (34.5924, -81.4524)
  coincident P58 P60
  coincident P61 L54
  parallel L29 L30
  coincident P62 L54
  parallel L28 L31
  coincident P54 P63
  coincident P64 L54
  parallel L27 L32
  coincident P52 P65
  coincident P66 L54
  parallel L26 L33
  coincident P50 P67
  coincident P68 L54
  parallel L25 L34
  coincident P48 P69
  coincident P70 L54
  parallel L24 L35
  coincident P46 P71
  coincident P72 L54
  parallel L23 L36
  coincident P44 P73
  coincident P74 L54
  parallel L22 L37
  coincident P42 P75
  coincident P76 L54
  parallel L21 L38
  coincident P40 P77
  coincident P78 L54
  parallel L20 L39
  coincident P79 L54
  parallel L19 L40
  coincident P36 P80
  coincident P81 L54
  parallel L18 L41
  coincident P38 P82
  coincident P56 P83
  coincident P34 P84
  coincident P85 L54
  parallel L17 L42
  coincident P32 P86
  coincident P87 L54
  parallel L16 L43
  coincident P30 P88
  coincident P89 L54
  parallel L15 L44
  coincident P28 P90
  coincident P91 L54
  parallel L14 L45
  coincident P26 P92
  coincident P93 L54
  coincident P24 P94
  coincident P95 L54
  coincident P22 P96
  parallel L11 L48
  coincident P97 L54
  parallel L12 L47
  parallel L13 L46
  coincident P20 P98
  coincident P99 L54
  parallel L10 L49
  coincident P18 P100
  coincident P101 L54
  parallel L9 L50
  coincident P16 P102
  coincident P103 L54
  coincident P104 L54
  parallel L7 L52
  coincident P12 P105
  coincident P106 L54
  parallel L6 L53
  parallel L8 L51
  coincident P14 P107
  collinear L54 L55
  collinear L55 L56
  collinear L56 L57
  collinear L57 L58
  collinear L58 L59
  collinear L59 L60
  collinear L60 L61
  collinear L61 L62
  collinear L62 L63
  collinear L63 L64
  collinear L64 L65
  collinear L65 L66
  collinear L66 L67
  collinear L67 L68
  collinear L68 L69
  collinear L69 L70
  collinear L70 L71
  collinear L71 L72
  collinear L72 L73
  collinear L73 L74
  collinear L74 L75
  collinear L75 L76
  coincident P91 L68
  coincident P79 L63
  midpoint P87 L66
  midpoint P85 L65
  midpoint P89 L67
  midpoint P91 L68
  midpoint P93 L69
  midpoint P95 L70
  midpoint P97 L71
  midpoint P99 L72
  midpoint P101 L73
  midpoint P103 L74
  midpoint P104 L75
  midpoint P106 L76
  midpoint P81 L64
  midpoint P79 L63
  midpoint P78 L62
  midpoint P76 L61
  midpoint P74 L60
  midpoint P72 L59
  midpoint P70 L58
  midpoint P68 L57
  midpoint P66 L56
  midpoint P64 L55
  midpoint P62 L54
  midpoint P61 L77
  collinear L54 L77
  parallel L76 L78
  midpoint L78 P158
  parallel L4 L77
  dimension "d1032" distance P106 P158 = 19.05
  dimension "d1047" distance L4 L77 = 2.54
  dimension "d996" Text1-Height = 3.175
  dimension "d997" Text2-Height = 3.175
  dimension "d998" Text3-Height = 3.175
  dimension "d999" Text4-Height = 3.175
  dimension "d1000" Text5-Height = 3.175
  dimension "d1001" Text6-Height = 3.175
  dimension "d1002" Text7-Height = 3.175
  dimension "d1003" Text8-Height = 3.175
  dimension "d1005" Text10-Height = 3.175
  dimension "d1006" Text11-Height = 3.175
  dimension "d1007" Text12-Height = 3.175
  dimension "d1008" Text13-Height = 3.175
  dimension "d1009" Text14-Height = 3.175
  dimension "d1033" Text14-Height = 3.175
sketch "Back_Hip-Valley_Text" plane through (0, 0, 0) normal (0, 1, 0) x axis (1, 0, 0)
  line L1 (177.8, 1.5875) -> (0, 1.5875)
  line L2 (0, 1.5875) -> (0, -176.2125)
  line L3 (34.5079, -85.129) -> (118.4665, -1.1704)
  line L4 (38.1, -88.7211) -> (122.0586, -4.7625)
  line L5 (0, -176.2125) -> (177.8, 1.5875)
  line L6 (48.0627, -67.982) -> (49.5505, -70.0864)
  line L7 (47.7139, -68.3308) -> (48.4116, -67.6332)
  line L8 (49.268, -66.7767) -> (50.7931, -68.8438)
  line L9 (48.9243, -67.1205) -> (49.6118, -66.433)
  line L10 (50.5381, -65.5067) -> (52.1025, -67.5344)
  line L11 (50.1827, -65.8621) -> (50.8935, -65.1513)
  line L12 (51.8626, -64.1822) -> (53.4679, -66.169)
  line L13 (51.3925, -64.6523) -> (52.3326, -63.7121)
  line L14 (53.2623, -62.7825) -> (54.911, -64.7259)
  line L15 (52.7738, -63.271) -> (53.7508, -62.294)
  line L16 (54.748, -61.2968) -> (56.4427, -63.1942)
  line L17 (54.2489, -61.7959) -> (55.247, -60.7977)
  line L18 (56.3105, -59.7343) -> (58.0535, -61.5834)
  line L19 (55.8285, -60.2162) -> (56.7924, -59.2524)
  line L20 (57.9718, -58.073) -> (59.7662, -59.8706)
  line L21 (57.3665, -58.6783) -> (58.577, -57.4678)
  line L22 (59.7343, -56.3105) -> (61.5834, -58.0535)
  line L23 (59.2472, -56.7975) -> (60.2214, -55.8234)
  line L24 (60.777, -55.2677) -> (62.4263, -53.6185)
  line L25 (61.6017, -54.4431) -> (63.5085, -56.1284)
  line L26 (63.0246, -53.0202) -> (64.1532, -51.8916)
  line L27 (63.5889, -52.4559) -> (65.5572, -54.0797)
  line L28 (65.7127, -50.3321) -> (67.7468, -51.8901)
  line L29 (65.1884, -50.8563) -> (66.237, -49.8078)
  line L30 (67.9716, -48.0732) -> (70.0756, -49.5613)
  line L31 (67.268, -48.7767) -> (68.6752, -47.3696)
  line L32 (69.9763, -46.0685) -> (70.8404, -45.2044)
  line L33 (70.4084, -45.6364) -> (72.5878, -47.0491)
  line L34 (73.0172, -43.0276) -> (75.2774, -44.3595)
  line L35 (72.0594, -43.9854) -> (73.975, -42.0698)
  line L36 (75.8281, -40.2167) -> (78.1753, -41.4616)
  line L37 (74.8024, -41.2424) -> (76.8537, -39.191)
  line L38 (78.866, -37.1788) -> (81.3072, -38.3296)
  line L39 (77.7876, -38.2571) -> (79.9443, -36.1004)
  line L40 (82.151, -33.8938) -> (84.694, -34.9429)
  line L41 (80.7488, -35.2959) -> (83.5532, -32.4916)
  line L42 (85.735, -30.3098) -> (88.3888, -31.2481)
  line L43 (84.4206, -31.6242) -> (87.0493, -28.9955)
  line L44 (89.631, -26.4138) -> (92.4054, -27.2315)
  line L45 (88.2354, -27.8094) -> (91.0265, -25.0183)
  line L46 (93.9137, -22.131) -> (96.8208, -22.8161)
  line L47 (92.1996, -23.8452) -> (95.6279, -20.4169)
  line L48 (97.292, -18.7528) -> (99.9177, -16.1271)
  line L49 (98.6048, -17.4399) -> (101.6571, -17.9798)
  line L50 (103.8128, -12.2319) -> (107.0263, -12.6106)
  line L51 (103.1183, -12.9265) -> (104.5074, -11.5374)
  line L52 (106.6227, -9.422) -> (109.9232, -9.7137)
  line L53 (105.3862, -10.6586) -> (107.8593, -8.1855)
  line L54 (28.4126, -87.6321) -> (40.7721, -75.2727)
  dimension "d1010" Text1-Height = 3.175
  dimension "d1011" Text2-Height = 3.175
  dimension "d1012" Text3-Height = 3.175
  dimension "d1013" Text4-Height = 3.175
  dimension "d1014" Text5-Height = 3.175
  dimension "d1015" Text6-Height = 3.175
  dimension "d1016" Text7-Height = 3.175
  dimension "d1017" Text8-Height = 3.175
  dimension "d1018" Text9-Height = 3.175
  dimension "d1019" Text10-Height = 3.175
  dimension "d1020" Text11-Height = 3.175
  dimension "d1021" Text12-Height = 3.175
  dimension "d1022" Text13-Height = 3.175
  dimension "d1034" Text14-Height = 3.175
sketch "Front_Logo" plane through (0, 0, 0) normal (0, 1, 0) x axis (1, 0, 0)
  line L1 (19.05, -134.7119) -> (19.05, -17.4625)
  line L2 (38.1, -23.8125) -> (38.1, -70.7606)
  line L3 (38.1, -97.7013) -> (38.1, -88.7211)
  line L4 (38.1, -88.7211) -> (38.1, -70.7606)
  line L5 (34.925, -23.8125) -> (34.925, -70.7606)
  line L6 (85.0481, -23.8125) -> (38.1, -23.8125)
  line L7 (97.7481, -11.1125) -> (12.7, -11.1125)
  line L8 (85.0481, -20.6375) -> (38.1, -20.6375)
  dimension "d1035" = -3.175
  dimension "d1037" = -3.175
  dimension "d1036" Text1-Height = 6.35
  dimension "d1038" Text2-Height = 6.35
sketch "Back_Logo" plane through (0, 0, 0) normal (0, 1, 0) x axis (1, 0, 0)
  line L1 (38.1, -23.8125) -> (38.1, -70.7606)
  line L2 (34.925, -23.8125) -> (34.925, -70.7606)
  line L3 (19.05, -134.7119) -> (19.05, -17.4625)
  line L4 (85.0481, -23.8125) -> (38.1, -23.8125)
  line L5 (85.0481, -20.6375) -> (38.1, -20.6375)
  line L6 (97.7481, -11.1125) -> (12.7, -11.1125)
  dimension "d1039" Text1-Height = 6.35
  dimension "d1040" Text2-Height = 6.35
extrude "Extrude1" new body sketch "MasterShape" profile of A1 L1 L2 L3 L4 L5 L6 L7 L8 L9 L10 L11 L12 L14 L15 L16 L17 L18 L20 L22 L24 L25 L26 distance 3.81 (= "Square_Thickness")
fillet "Fillet1" radius 1.5875
extrude "Extrude2" add sketch "MasterShape" profile of L1 L4 L5 L6 L7 distance 15.875 (= "Square_Fense_Thickness")
extrude "Extrude3" sketch "Inch_Scale" profile of L1 A1 L15 A2 L16 A3 L17 A4 L18 A5 A6 L20 A7 A8 L21 A9 A10 L22 A11 A12 L26 A13 L27 A14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 no distance stored
extrude "Extrude4" sketch "Inch_Scale" profile of L1 A1 L15 A2 L16 A3 L17 A4 L18 A5 A6 L20 A7 A8 L21 A9 A10 L22 A11 A12 L26 A13 L27 A14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 blind 0.254 (= "Scale_Rule_Depth")
rectangular_pattern "R-Pattern1" vSpaceDistance 0
extrude "Extrude1" sketch "Front_Scale_Text" no distance stored
extrude "Extrude9" sketch "Back_Scale_Text" no distance stored
extrude "Extrude5" sketch "Inch_Scale" profile of L12 L39 A17 L40 A18 L42 A19 L43 A20 L45 A21 L46 A22 L48 A23 L49 A24 no distance stored
extrude "Extrude6" sketch "Inch_Scale" profile of L12 L39 A17 L40 A18 L42 A19 L43 A20 L45 A21 L46 A22 L48 A23 L49 A24 blind 0.254 (= "Scale_Rule_Depth")
rectangular_pattern "R-Pattern2" uSpaceDistance 12.7 (= "Scale_Rule_Span * 0.5") vSpaceDistance 0
extrude "Extrude10" sketch "Front_Scale_Text" no distance stored
extrude "Extrude11" sketch "Back_Scale_Text" no distance stored
chamfer "Chamfer1" distance 1.905 (= "Square_Thickness * 0.5") Rotate Angle 30
extrude "Extrude7" cut sketch "Inch_Scale" profile of L4 L5 L52 L53 L54 L58 L59 L60 distance 3.81 (= "Square_Thickness")
rectangular_pattern "R-Pattern3" vSpaceDistance 0
extrude "Extrude12" sketch "Angular_Degree_Scale" blind 0.254 (= "Scale_Rule_Depth")
extrude "Extrude13" sketch "Angular_Degree_Scale" no distance stored
extrude "Extrude14" sketch "Angular_Common_Rafter" blind 0.254 (= "Scale_Rule_Depth")
extrude "Extrude15" sketch "Angular_Common_Rafter" blind 0.254 (= "Scale_Rule_Depth")
extrude "Extrude16" sketch "Angular_Common_Rafter" no distance stored
extrude "Extrude17" sketch "Angular_Common_Rafter" no distance stored
extrude "Extrude18" sketch "Angular_Hip_Valley" blind 0.254 (= "Scale_Rule_Depth")
extrude "Extrude19" sketch "Angular_Hip_Valley" blind 0.254 (= "Scale_Rule_Depth")
extrude "Extrude20" sketch "Angular_Hip_Valley" no distance stored
extrude "Extrude21" sketch "Angular_Hip_Valley" no distance stored
extrude "Extrude22" sketch "Front_Angular_Scale_Text" no distance stored
extrude "Extrude23" sketch "Back_Angular_Text" no distance stored
extrude "Extrude24" sketch "Front_Common_Rafter_Text" no distance stored
extrude "Extrude25" sketch "Back_Common_Rafter_Text" no distance stored
extrude "Extrude26" sketch "Front_Hip-Valley_Text" no distance stored
extrude "Extrude27" sketch "Back_Hip-Valley_Text" no distance stored
extrude "Extrude28" sketch "Front_Logo" no distance stored
extrude "Extrude29" sketch "Back_Logo" no distance stored
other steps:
extrude "Extrude8" sketch "Front_Scale_Text" no distance stored
create_component "CreateComponent1"
create_component "CreateComponent2"
create_component "CreateComponent3"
